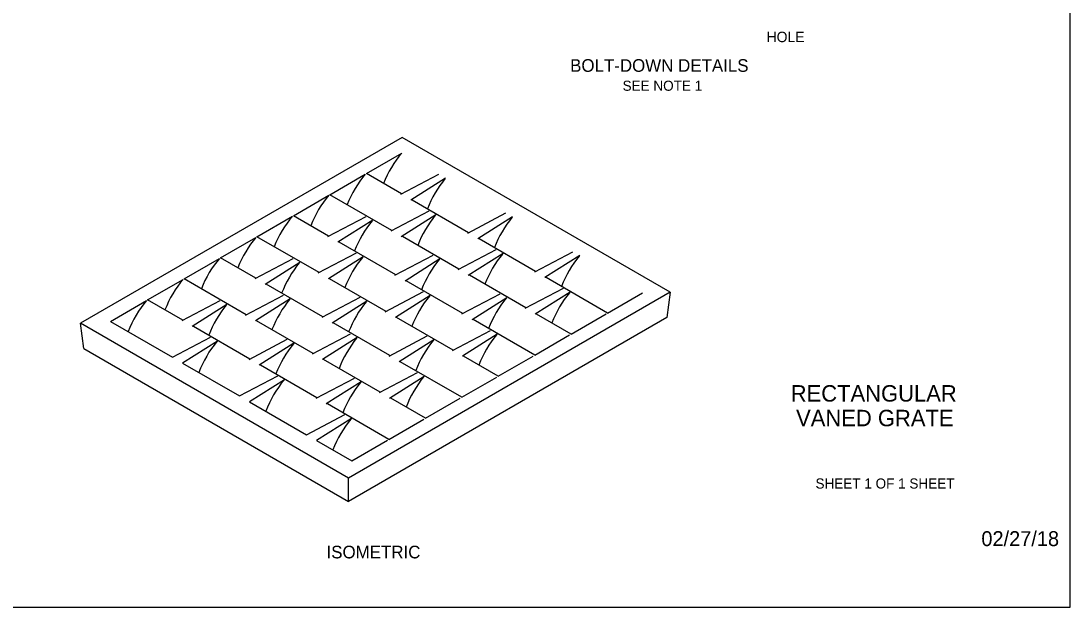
# Model space of a CAD drawing. Extents: x 99862 to 103151, y 100000 to 102076.
# Drawn here: x 101491 to 103151, y 100000 to 100926 of the extents above; entities that cross this region are included whole.
import ezdxf

# ---------------------------------------------------------------- set-up
doc = ezdxf.new("R2010")
doc.units = 0
for name, color, linetype in [('Level 1', 7, 'Continuous'), ('Level 20', 7, 'Continuous'), ('Level 6', 7, 'Continuous'), ('Level 62', 7, 'Continuous')]:
    doc.layers.add(name, color=color, linetype=linetype)

msp = doc.modelspace()

# ---------------------------------------------------------------- linework, layer by layer
at = {"layer": 'Level 1'}
msp.add_lwpolyline([(99862, 99999.5), (103151, 99999.5), (103151, 102075.5), (99862, 102075.5)], close=True, dxfattribs=at)
at = {"layer": 'Level 6'}
for p, q in [((102093.9, 100742), (101584.8, 100448.1)), ((102518.2, 100497.1), (102093.9, 100742)), ((102037.4, 100684.8), (102093.4, 100717.2)), ((101979.7, 100651.5), (102035.7, 100683.9)), ((102093.1, 100652.7), (102037.4, 100684.8)), ((102091.9, 100652.1), (102152.3, 100683.8)), ((102162.9, 100677.7), (102107.9, 100642.9)), ((101922, 100618.3), (101978, 100650.6)), ((102077.8, 100594.9), (101979.7, 100651.5)), ((102199.2, 100591.4), (102109.7, 100643.1)), ((102076.7, 100594.3), (102137, 100626)), ((101864.3, 100585), (101920.3, 100617.3)), ((101977.7, 100586.1), (101922, 100618.3)), ((101976.6, 100585.5), (102036.9, 100617.2)), ((102047.5, 100611.1), (101992.5, 100576.3)), ((102147.6, 100619.9), (102092.6, 100585.1)), ((102198, 100590.8), (102258.3, 100622.6)), ((102268.9, 100616.5), (102213.9, 100581.6)), ((101806.7, 100551.7), (101862.7, 100584)), ((101962.5, 100528.3), (101864.3, 100585)), ((102083.8, 100524.8), (101994.3, 100576.5)), ((102183.9, 100533.6), (102094.4, 100585.3)), ((102305.2, 100530.2), (102215.7, 100581.9)), ((101961.4, 100527.7), (102021.7, 100559.4)), ((102182.8, 100533), (102243.1, 100564.8)), ((102253.7, 100558.7), (102198.7, 100523.8)), ((102304.1, 100529.6), (102364.4, 100561.4)), ((101749, 100518.4), (101805, 100550.7)), ((101862.4, 100519.5), (101806.7, 100551.7)), ((101861.3, 100518.9), (101921.6, 100550.6)), ((101932.2, 100544.5), (101877.2, 100509.7)), ((102032.3, 100553.3), (101977.3, 100518.5)), ((102082.7, 100524.2), (102143, 100556)), ((102153.6, 100549.9), (102098.6, 100515)), ((102375, 100555.2), (102320, 100520.4)), ((102290, 100472.4), (102200.5, 100524.1)), ((101691.3, 100485.1), (101747.3, 100517.4)), ((101847.2, 100461.7), (101749, 100518.4)), ((101968.5, 100458.2), (101879, 100509.9)), ((102068.6, 100467), (101979.1, 100518.7)), ((102189.9, 100463.6), (102100.4, 100515.3)), ((102419.2, 100464.4), (102321.8, 100520.6)), ((101846, 100461.1), (101906.3, 100492.8)), ((102518.2, 100497.1), (102009.1, 100203.1)), ((102067.4, 100466.4), (102127.7, 100498.2)), ((102138.4, 100492.1), (102083.3, 100457.3)), ((102188.7, 100463), (102249.1, 100494.8)), ((102288.8, 100471.8), (102349.2, 100503.6)), ((102359.8, 100497.4), (102304.7, 100462.6)), ((102419.2, 100464.4), (102474.4, 100496.3)), ((102518.2, 100497.1), (102512.9, 100457.3)), ((101632.5, 100451.1), (101689.7, 100484.1)), ((101747.1, 100452.9), (101691.3, 100485.1)), ((101745.9, 100452.3), (101806.2, 100484)), ((101816.8, 100477.9), (101761.8, 100443.1)), ((101916.9, 100486.7), (101861.9, 100451.9)), ((101967.3, 100457.6), (102027.6, 100489.4)), ((102038.3, 100483.3), (101983.2, 100448.4)), ((102259.7, 100488.6), (102204.6, 100453.8)), ((102512.9, 100457.3), (102009.1, 100166.4)), ((102174.6, 100405.8), (102085.1, 100457.5)), ((102361.5, 100431.1), (102306.6, 100462.8)), ((102361.5, 100431.1), (102416.8, 100463)), ((102009.1, 100203.1), (101584.8, 100448.1)), ((101590.1, 100408.3), (101584.8, 100448.1)), ((101632.5, 100451.1), (101730.7, 100394.5)), ((101853.1, 100391.6), (101763.6, 100443.3)), ((101953.2, 100400.4), (101863.7, 100452.1)), ((102074.5, 100397), (101985, 100448.7)), ((102303.9, 100397.8), (102206.5, 100454)), ((101730.7, 100394.5), (101791, 100426.3)), ((101952.1, 100399.8), (102012.4, 100431.6)), ((102023, 100425.5), (101968, 100390.7)), ((102073.4, 100396.4), (102133.7, 100428.2)), ((102173.5, 100405.2), (102233.8, 100437)), ((102244.4, 100430.8), (102189.4, 100396)), ((102303.9, 100397.8), (102359.1, 100429.7)), ((101590.1, 100408.3), (102009.1, 100166.4)), ((101801.6, 100420.1), (101746.6, 100385.3)), ((101852, 100391), (101912.3, 100422.8)), ((101922.9, 100416.7), (101867.9, 100381.9)), ((102144.3, 100422), (102089.3, 100387.2)), ((102059.3, 100339.2), (101969.8, 100390.9)), ((102246.2, 100364.5), (102191.2, 100396.2)), ((102246.2, 100364.5), (102301.4, 100396.4)), ((101746.6, 100385.3), (101836.7, 100333.2)), ((101959.2, 100330.4), (101869.7, 100382.1)), ((102188.5, 100331.2), (102091.1, 100387.4)), ((101836.7, 100333.2), (101897.1, 100365)), ((101907.7, 100358.9), (101852.6, 100324.1)), ((101958, 100329.8), (102018.4, 100361.6)), ((102058.1, 100338.6), (102118.5, 100370.4)), ((102129.1, 100364.2), (102074, 100329.4)), ((102188.5, 100331.2), (102243.7, 100363.1)), ((102029, 100355.4), (101973.9, 100320.6)), ((101852.6, 100324.1), (101942.8, 100272)), ((102130.8, 100297.9), (102075.9, 100329.6)), ((102130.8, 100297.9), (102186.1, 100329.8)), ((102073.2, 100264.6), (101975.8, 100320.8)), ((101942.8, 100272), (102003.1, 100303.8)), ((102013.7, 100297.7), (101958.7, 100262.8)), ((102073.2, 100264.6), (102128.4, 100296.5)), ((101958.7, 100262.8), (102014.4, 100230.7)), ((102014.4, 100230.7), (102070.7, 100263.2)), ((102009.1, 100166.4), (102009.1, 100203.1))]:
    msp.add_line(p, q, dxfattribs=at)
for centre, major_axis, ratio, start_param, end_param in [((102128.9, 100653.4), (45.9, 94.6), 0.619773, 1.161599, 1.703913), ((102071.2, 100620.1), (45.9, 94.6), 0.619773, 1.161599, 1.703913), ((102193.7, 100616.1), (46.1, 94.5), 0.569297, 1.174658, 1.709128), ((102013.6, 100586.8), (45.9, 94.6), 0.619773, 1.161599, 1.703913), ((102108, 100639.8), (1.65, 3.38), 0.569297, 6.243649, 7.029047), ((101955.9, 100553.5), (45.9, 94.6), 0.619773, 1.161599, 1.703913), ((102078.3, 100549.5), (46.1, 94.5), 0.569297, 1.174658, 1.709128), ((102178.4, 100558.3), (46.1, 94.5), 0.569297, 1.174658, 1.709128), ((102147.7, 100616.8), (1.65, 3.38), 0.569297, 0.745861, 1.174658), ((102299.7, 100554.8), (46.1, 94.5), 0.569297, 1.174658, 1.709128), ((102269, 100613.4), (1.65, 3.38), 0.569297, 0.745861, 1.174658), ((101898.2, 100520.2), (45.9, 94.6), 0.619773, 1.161599, 1.703913), ((101992.6, 100573.2), (1.65, 3.38), 0.569297, 6.243649, 7.029047), ((102092.7, 100582), (1.65, 3.38), 0.569297, 6.243649, 7.029047), ((102214, 100578.5), (1.65, 3.38), 0.569297, 6.243649, 7.029047), ((102284.5, 100497), (46.1, 94.5), 0.569297, 1.174658, 1.709128), ((102253.8, 100555.6), (1.65, 3.38), 0.569297, 0.745861, 1.174658), ((101840.5, 100487), (45.9, 94.6), 0.619773, 1.161599, 1.703913), ((101963, 100482.9), (46.1, 94.5), 0.569297, 1.174658, 1.709128), ((102063.1, 100491.7), (46.1, 94.5), 0.569297, 1.174658, 1.709128), ((102032.4, 100550.2), (1.65, 3.38), 0.569297, 0.745861, 1.174658), ((102184.4, 100488.2), (46.1, 94.5), 0.569297, 1.174658, 1.709128), ((102153.7, 100546.8), (1.65, 3.38), 0.569297, 0.745861, 1.174658), ((102405.8, 100493.6), (46.1, 94.5), 0.569297, 1.174658, 1.709128), ((102375.1, 100552.1), (1.65, 3.38), 0.569297, 0.745861, 1.174658), ((102198.8, 100520.7), (1.65, 3.38), 0.569297, 6.243649, 7.029047), ((101782.9, 100453.7), (45.9, 94.6), 0.619773, 1.161599, 1.703913), ((101877.3, 100506.6), (1.65, 3.38), 0.569297, 6.243649, 7.029047), ((101977.4, 100515.4), (1.65, 3.38), 0.569297, 6.243649, 7.029047), ((102098.7, 100511.9), (1.65, 3.38), 0.569297, 6.243649, 7.029047), ((102320.1, 100517.3), (1.65, 3.38), 0.569297, 6.243649, 7.029047), ((102169.1, 100430.4), (46.1, 94.5), 0.569297, 1.174658, 1.709128), ((102138.4, 100489), (1.65, 3.38), 0.569297, 0.745861, 1.174658), ((102390.6, 100435.8), (46.1, 94.5), 0.569297, 1.174658, 1.709128), ((102359.9, 100494.3), (1.65, 3.38), 0.569297, 0.745861, 1.174658), ((101725.2, 100420.4), (45.9, 94.6), 0.619773, 1.161599, 1.714552), ((101847.6, 100416.3), (46.1, 94.5), 0.569297, 1.174658, 1.709128), ((101947.7, 100425.1), (46.1, 94.5), 0.569297, 1.174658, 1.709128), ((101917, 100483.6), (1.65, 3.38), 0.569297, 0.745861, 1.174658), ((102069, 100421.6), (46.1, 94.5), 0.569297, 1.174658, 1.709128), ((102038.3, 100480.2), (1.65, 3.38), 0.569297, 0.745861, 1.174658), ((102290.5, 100427), (46.1, 94.5), 0.569297, 1.174658, 1.709128), ((102259.8, 100485.5), (1.65, 3.38), 0.569297, 0.745861, 1.174658), ((102083.4, 100454.1), (1.65, 3.38), 0.569297, 6.243649, 7.029047), ((102304.8, 100459.5), (1.65, 3.38), 0.569297, 6.243649, 7.029047), ((101761.9, 100440), (1.65, 3.38), 0.569297, 6.243649, 7.029047), ((101862, 100448.8), (1.65, 3.38), 0.569297, 6.243649, 7.029047), ((101983.3, 100445.3), (1.65, 3.38), 0.569297, 6.243649, 7.029047), ((102204.7, 100450.7), (1.65, 3.38), 0.569297, 6.243649, 7.029047), ((102053.8, 100363.8), (46.1, 94.5), 0.569297, 1.174658, 1.709128), ((102023.1, 100422.4), (1.65, 3.38), 0.569297, 0.745861, 1.174658), ((102275.2, 100369.2), (46.1, 94.5), 0.569297, 1.174658, 1.709128), ((102244.5, 100427.7), (1.65, 3.38), 0.569297, 0.745861, 1.174658), ((101832.4, 100358.5), (46.1, 94.5), 0.569297, 1.174658, 1.719767), ((101801.7, 100417), (1.65, 3.38), 0.569297, 0.745861, 1.174658), ((101953.7, 100355), (46.1, 94.5), 0.569297, 1.174658, 1.709128), ((101923, 100413.6), (1.65, 3.38), 0.569297, 0.745861, 1.174658), ((102175.1, 100360.4), (46.1, 94.5), 0.569297, 1.174658, 1.709128), ((102144.4, 100418.9), (1.65, 3.38), 0.569297, 0.745861, 1.174658), ((101968.1, 100387.5), (1.65, 3.38), 0.569297, 6.243649, 7.029047), ((102189.5, 100392.9), (1.65, 3.38), 0.569297, 6.243649, 7.029047), ((101868, 100378.7), (1.65, 3.38), 0.569297, 6.243649, 7.029047), ((102089.4, 100384.1), (1.65, 3.38), 0.569297, 6.243649, 7.029047), ((101938.4, 100297.2), (46.1, 94.5), 0.569297, 1.174658, 1.719767), ((101907.8, 100355.8), (1.65, 3.38), 0.569297, 0.745861, 1.174658), ((102159.9, 100302.6), (46.1, 94.5), 0.569297, 1.174658, 1.709128), ((102129.2, 100361.1), (1.65, 3.38), 0.569297, 0.745861, 1.174658), ((102059.8, 100293.8), (46.1, 94.5), 0.569297, 1.174658, 1.709128), ((102029.1, 100352.3), (1.65, 3.38), 0.569297, 0.745861, 1.174658), ((102074.1, 100326.3), (1.65, 3.38), 0.569297, 6.243649, 7.029047), ((101974, 100317.5), (1.65, 3.38), 0.569297, 6.243649, 7.029047), ((102044.5, 100236), (46.1, 94.5), 0.569297, 1.174658, 1.719767), ((102013.8, 100294.5), (1.65, 3.38), 0.569297, 0.745861, 1.174658)]:
    msp.add_ellipse(centre, major_axis=major_axis, ratio=ratio, start_param=start_param, end_param=end_param, dxfattribs=at)

# ---------------------------------------------------------------- texts
at = {"layer": 'Level 1'}
msp.add_text('HOLE', height=16.5, dxfattribs=at).set_placement((102670.8, 100892.7))
at = {"layer": 'Level 20'}
for s, p in [('BOLT-DOWN DETAILS', (102359.9, 100845.8)), ('ISOMETRIC', (101974.4, 100076.4))]:
    msp.add_text(s, height=20, dxfattribs=at).set_placement(p)
at = {"layer": 'Level 62'}
for s, height, p in [('SEE NOTE 1', 16, (102442.9, 100815.8)), ('RECTANGULAR', 26, (102709, 100324.3)), ('VANED GRATE', 26, (102717.5, 100285.3)), ('SHEET 1 OF 1 SHEET', 16, (102748.2, 100186.8)), ('02/27/18', 23.62, (103010.7, 100095.8))]:
    msp.add_text(s, height=height, dxfattribs=at).set_placement(p)

doc.saveas('drawing.dxf')
